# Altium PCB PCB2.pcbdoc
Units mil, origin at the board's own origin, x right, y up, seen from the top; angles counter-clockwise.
Board outline 866.1 x 519.7 mil, 2 copper layers (Top Layer, Bottom Layer), stack 62.2 mil thick; 5 components, 7 nets, 24 pads, 0 vias.
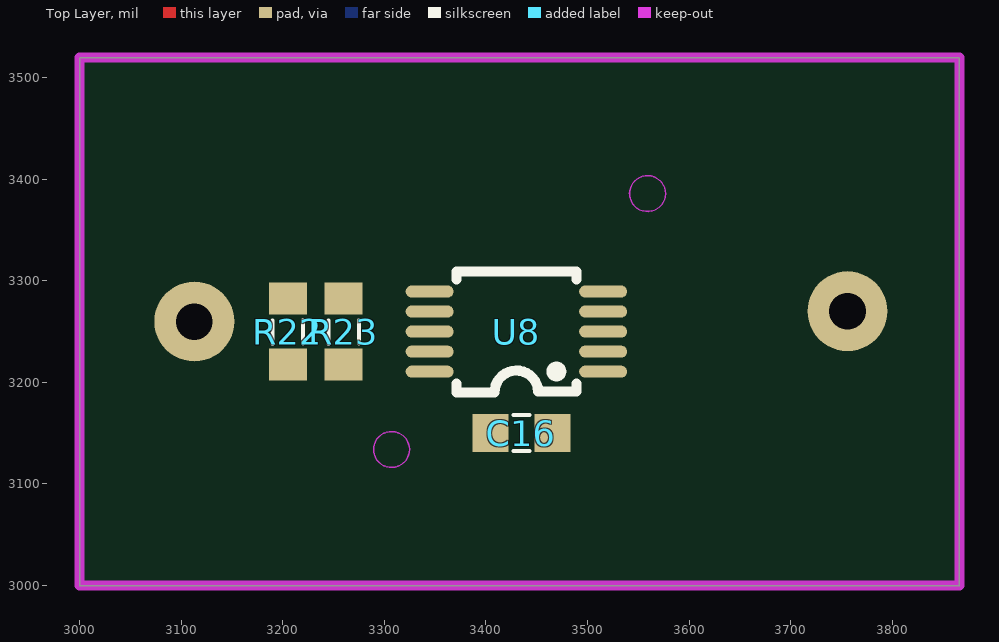
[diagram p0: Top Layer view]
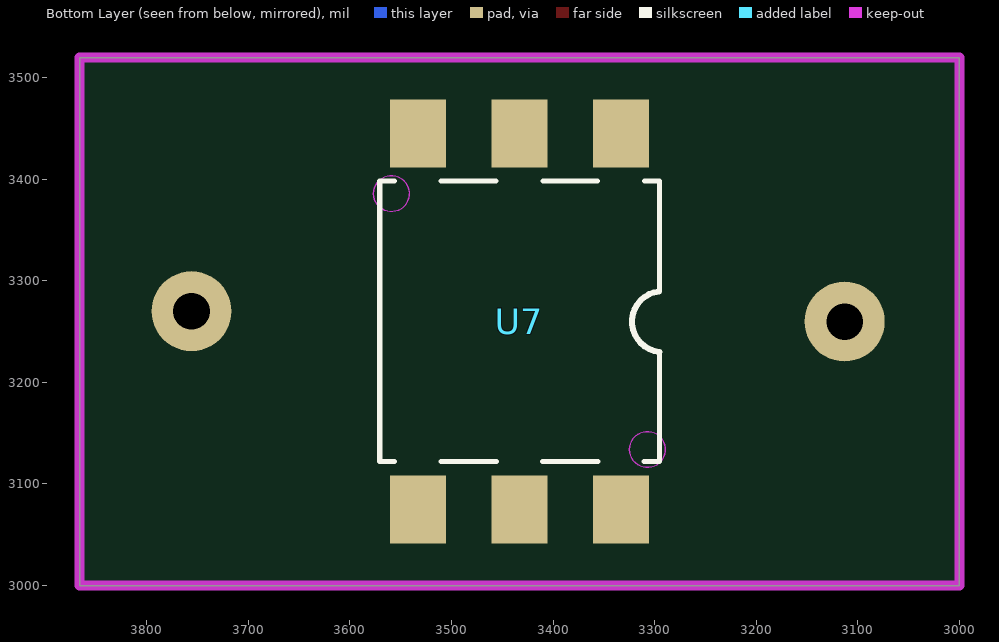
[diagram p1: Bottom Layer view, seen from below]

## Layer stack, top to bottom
Top Solder Mask Layer: solder mask 0.4, Dk 3.3
Top Layer: signal copper 1.4
Dielectric1: surface 59.4, FR4, Dk 4.5
Bottom Layer: signal copper 1.4
Bottom Solder Mask Layer: solder mask 0.4, Dk 3.3

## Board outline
3000,3000 3000,3519.7 3866.1,3519.7 3866.1,3000

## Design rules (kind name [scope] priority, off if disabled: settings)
BoardOutlineClearance copperThickness1oz [All] p0: genericclearance=10 ignorepadtopadclearanceinfootprint=FALSE except(0: Arc-SplitContinuation Track-SplitContinuation SMDPad-SplitContinuation THPad-SplitContinuation Via-SplitContinuation Fill-SplitContinuation Poly-SplitContinuation Region-SplitContinuation Text-SplitContinuation)
BoardOutlineClearance copperThickness2oz [All] p0: genericclearance=10 ignorepadtopadclearanceinfootprint=FALSE except(0: Arc-SplitContinuation Track-SplitContinuation SMDPad-SplitContinuation THPad-SplitContinuation Via-SplitContinuation Fill-SplitContinuation Poly-SplitContinuation Region-SplitContinuation Text-SplitContinuation)
BoardOutlineClearance otherClearance [All] p0: genericclearance=10 ignorepadtopadclearanceinfootprint=FALSE except(0: Arc-SplitContinuation Track-SplitContinuation SMDPad-SplitContinuation THPad-SplitContinuation Via-SplitContinuation Fill-SplitContinuation Poly-SplitContinuation Region-SplitContinuation Text-SplitContinuation)
Clearance copperThickness1oz [All] p1: gap=7 ignorepadtopadclearanceinfootprint=FALSE
Clearance copperThickness2oz [All] p1: gap=7 ignorepadtopadclearanceinfootprint=FALSE
Clearance otherClearance [All] p1: gap=7 ignorepadtopadclearanceinfootprint=FALSE
DiffPairsRouting differentialPair [All] p1: maxuncoupledlength=10 minlimit=6 maxlimit=Infinity mostfreqgap=6 toplayer_minwidth=5 toplayer_prefwidth=10 toplayer_maxwidth=100 bottomlayer_minwidth=5 bottomlayer_prefwidth=10 bottomlayer_maxwidth=100
PasteMaskExpansion pasteMaskExpansion [All] p1: expansion=0
PlaneConnect innerPlane [All] p1: planeconnectstyle=Relief reliefexpansion=20 reliefentries=4 reliefconductorwidth=10 reliefairgap=10
PolygonConnect copperRegion [All] p1: connectstyle=Relief reliefentries=4 reliefconductorwidth=10 polygonreliefangle="90 Angle" airgapwidth=10
RoutingVias viaSize [All] p1: viastyle="Through Hole" holewidth=12.0078 minholewidth=11.811 maxholewidth=248.0314 width=12.0078 minwidth=11.811 maxwidth=248.0314
SolderMaskExpansion solderMaskExpansion [IsVia] p1: useseparateexpansions=TRUE expansion=-1000 expansionbottom=-1000
SolderMaskExpansion solderMaskExpansion [All] p2: useseparateexpansions=TRUE expansion=2 expansionbottom=2
Width copperThickness1oz [All] p1: maxlimit=100 minlimit=5 preferedwidth=10
Width copperThickness2oz [All] p1: maxlimit=100 minlimit=8 preferedwidth=10

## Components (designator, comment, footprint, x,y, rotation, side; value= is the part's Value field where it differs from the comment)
C16 "100nF" C0603 3435,3150 r180 top
R22 "10K" R0603 3205,3250 r90 top
R23 "10K" R0603 3260,3250 r90 top
U7 "GZP160-040S" SOP-6_L7.0-W7.0-P2.54-LS10.6-BL_GZP160-101S 3433.1,3259.8 r0 bottom
U8 "SGM58031XMS10G/TR" MSOP-10_L3.0-W3.0-P0.50-LS4.9-BL 3430,3250 r90 top

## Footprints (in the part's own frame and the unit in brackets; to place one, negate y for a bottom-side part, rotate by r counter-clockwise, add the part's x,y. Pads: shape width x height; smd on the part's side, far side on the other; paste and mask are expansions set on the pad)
C0603 [mil]
  rect 35.4x37.4 smd: 1(-30.5,0) 2(30.5,0)
  silkscreen extent -8,-18 8,18
MSOP-10_L3.0-W3.0-P0.50-LS4.9-BL [mil]
  oval 11.8x47.2 smd: 1(-39.4,-85.4) 2(-19.7,-85.4) 3(0,-85.4) 4(19.7,-85.4) 5(39.4,-85.4) 6(39.4,85.4) 7(19.7,85.4) 8(0,85.4) 9(-19.7,85.4) 10(-39.4,85.4)
  silkscreen extent -60,-59 59,59
R0603 [mil]
  rect 31.5x37.4 smd: 1(-32.5,0) 2(32.5,0)
  silkscreen extent -12,-15 12,15
SOP-6_L7.0-W7.0-P2.54-LS10.6-BL_GZP160-101S [mil]
  rect 55.1x66.9 smd paste+0 mask+2: 1(-100,-185.1) 2(0,-185.1) 3(100,-185.1) 4(100,185) 5(0,185) 6(-100,185)
  Board Outline Layer circle w0.1: c-126,125.9 r17.7
  Board Outline Layer circle w0.1: c126,-126 r17.7
  Board Outline Layer region: -108.3,125.9 -110.05,133.58 -114.96,139.74 -122.06,143.16 -129.94,143.16 -137.04,139.74 -141.95,133.58 -143.7,125.9 -143.7,125.9 -141.95,118.22 -137.04,112.06 -129.94,108.64 -122.06,108.64 -114.96,112.06 -110.05,118.22 -108.3,125.9
  Board Outline Layer region: -108.3,125.9 -110.05,133.58 -114.96,139.74 -122.06,143.16 -129.94,143.16 -137.04,139.74 -141.95,133.58 -143.7,125.9 -143.7,125.9 -141.95,118.22 -137.04,112.06 -129.94,108.64 -122.06,108.64 -114.96,112.06 -110.05,118.22 -108.3,125.9
  Board Outline Layer region: 143.7,-126 141.95,-118.32 137.04,-112.16 129.94,-108.74 122.06,-108.74 114.96,-112.16 110.05,-118.32 108.3,-126 108.2,-126 110.05,-133.68 114.96,-139.84 122.06,-143.26 129.94,-143.26 137.04,-139.84 141.95,-133.68 143.7,-126
  Board Outline Layer region: 143.7,-126 141.95,-118.32 137.04,-112.16 129.94,-108.74 122.06,-108.74 114.96,-112.16 110.05,-118.32 108.3,-126 108.2,-126 110.05,-133.68 114.96,-139.84 122.06,-143.26 129.94,-143.26 137.04,-139.84 141.95,-133.68 143.7,-126
  silkscreen extent -138,-138 138,138

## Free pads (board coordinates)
  round 78.7 hole 36: 1(3113,3259.8) 1(3755.9,3270)

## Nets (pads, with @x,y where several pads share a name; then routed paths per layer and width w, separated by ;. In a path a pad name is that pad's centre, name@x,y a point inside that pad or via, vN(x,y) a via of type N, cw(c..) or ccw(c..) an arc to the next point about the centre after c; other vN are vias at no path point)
AIN1: U7.4 U8.6
AIN3: U7.6 U8.7
BPM: U8.2
BPM_SCL: R22.1 U8.10
BPM_SDA: R23.1 U8.9
GND: C16.1 U7.2 U8.1 U8.3 U8.4 U8.5
VDD: C16.2 R22.2 R23.2 U7.5 U8.8
pads on no net: U7.1 U7.3

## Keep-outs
Board Outline Layer:
  the board outline again, w10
